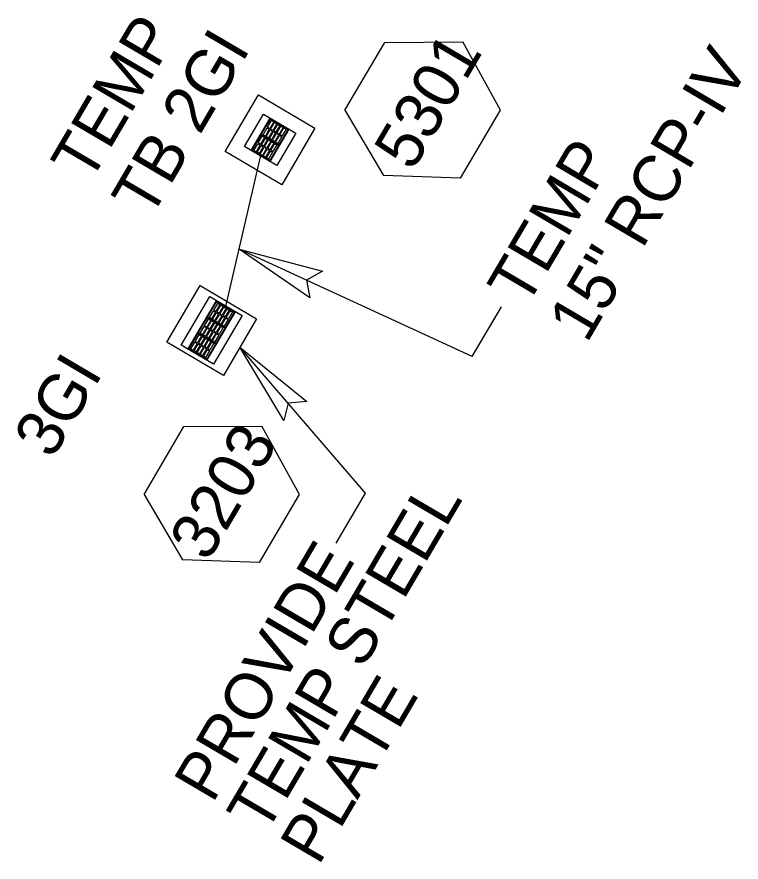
# Model space of a CAD drawing. Extents: x 2214419 to 2238519, y 983271 to 1015868.
# Drawn here: x 2234329 to 2234406.2, y 1008765.9 to 1008856 of the extents above; entities that cross this region are included whole.
import ezdxf

# ---------------------------------------------------------------- set-up
doc = ezdxf.new("R2010")
doc.units = 0
for name, color, linetype in [('Prop Drainage Structure Box Number Symbol CELL', 7, 'Continuous'), ('Prop Drainage Structure Drop Inlet Grate 2 Wide Slots and Sag Grates 840 22 TB CELL', 7, 'Continuous'), ('Prop Drainage Structure Drop Inlet Grate 2 Wide Slots and Sag Grates 840 22 TB Label', 7, 'Continuous'), ('Prop Drainage Structure Drop Inlet Grate 3 Wide Slots and Sag Grates 840 22 CELL', 7, 'Continuous'), ('Prop Drainage Structure Drop Inlet Grate 3 Wide Slots and Sag Grates 840 22 Label', 7, 'Continuous'), ('Prop Drainage Structure Pipe RCP 15in Class IV', 7, 'Continuous'), ('Prop Drainage Structure Pipe RCP 15in Class IV Label', 7, 'Continuous'), ('Prop Drainage Structure Plot Symbol 20 Scale', 7, 'Continuous'), ('Prop Drainage Structure Plot Symbol 20 Scale CELL', 7, 'Continuous'), ('Prop Drainage Structure Plot Symbol 50 Scale', 7, 'Continuous'), ('Prop Drainage Structure Plot Symbol 50 Scale CELL', 7, 'Continuous'), ('Prop Plan Preparation Drainage Notes Label', 7, 'Continuous')]:
    doc.layers.add(name, color=color, linetype=linetype)

msp = doc.modelspace()

# ---------------------------------------------------------------- linework, layer by layer
at = {"layer": 'Prop Drainage Structure Box Number Symbol CELL'}
for p, q in [((2234363.953, 1008846.059), (2234368.209, 1008853.299)), ((2234368.209, 1008853.299), (2234376.525, 1008853.361)), ((2234380.516, 1008846.064), (2234376.525, 1008853.361)), ((2234363.953, 1008846.059), (2234368.061, 1008839.1)), ((2234376.261, 1008838.825), (2234380.516, 1008846.064)), ((2234376.261, 1008838.825), (2234368.061, 1008839.1)), ((2234342.532, 1008805.092), (2234346.788, 1008812.332)), ((2234346.788, 1008812.332), (2234355.104, 1008812.394)), ((2234359.095, 1008805.097), (2234355.104, 1008812.394)), ((2234342.532, 1008805.092), (2234346.639, 1008798.133)), ((2234354.84, 1008797.858), (2234359.095, 1008805.097)), ((2234354.84, 1008797.858), (2234346.639, 1008798.133))]:
    msp.add_line(p, q, dxfattribs=at)
at = {"layer": 'Prop Drainage Structure Drop Inlet Grate 2 Wide Slots and Sag Grates 840 22 TB CELL'}
for p, q in [((2234356.981, 1008844.633), (2234356.981, 1008844.633)), ((2234354.961, 1008843.5), (2234354.961, 1008843.5)), ((2234355.967, 1008842.909), (2234355.967, 1008842.909)), ((2234356.973, 1008842.318), (2234356.973, 1008842.318)), ((2234354.954, 1008841.185), (2234354.954, 1008841.185))]:
    msp.add_line(p, q, dxfattribs=at)
for points in [[(2234357.986, 1008844.042), (2234355.959, 1008840.594), (2234353.948, 1008841.776), (2234355.975, 1008845.225), (2234357.986, 1008844.042)], [(2234357.901, 1008844.02), (2234355.937, 1008840.679), (2234354.033, 1008841.798), (2234355.997, 1008845.139), (2234357.901, 1008844.02), (2234357.901, 1008844.02)], [(2234357.887, 1008844.016), (2234356.915, 1008842.364), (2234355.03, 1008843.472), (2234356.001, 1008845.125), (2234357.887, 1008844.016)], [(2234356.354, 1008844.821), (2234355.931, 1008844.102), (2234355.698, 1008844.24), (2234356.12, 1008844.958), (2234356.354, 1008844.821)], [(2234356.686, 1008844.625), (2234356.264, 1008843.907), (2234356.03, 1008844.044), (2234356.453, 1008844.763), (2234356.686, 1008844.625)], [(2234357.018, 1008844.43), (2234356.596, 1008843.712), (2234356.363, 1008843.849), (2234356.785, 1008844.567), (2234357.018, 1008844.43)], [(2234357.351, 1008844.235), (2234356.928, 1008843.516), (2234356.695, 1008843.654), (2234357.117, 1008844.372), (2234357.351, 1008844.235)], [(2234356.905, 1008842.346), (2234355.934, 1008840.694), (2234354.048, 1008841.802), (2234355.019, 1008843.454), (2234356.905, 1008842.346)], [(2234355.889, 1008844.03), (2234355.467, 1008843.312), (2234355.233, 1008843.449), (2234355.656, 1008844.168), (2234355.889, 1008844.03)], [(2234356.222, 1008843.835), (2234355.799, 1008843.117), (2234355.566, 1008843.254), (2234355.988, 1008843.972), (2234356.222, 1008843.835)], [(2234356.554, 1008843.64), (2234356.131, 1008842.921), (2234355.898, 1008843.059), (2234356.32, 1008843.777), (2234356.554, 1008843.64)], [(2234356.886, 1008843.445), (2234356.464, 1008842.726), (2234356.23, 1008842.863), (2234356.653, 1008843.582), (2234356.886, 1008843.445)], [(2234357.218, 1008843.249), (2234356.796, 1008842.531), (2234356.563, 1008842.668), (2234356.985, 1008843.386), (2234357.218, 1008843.249)], [(2234357.683, 1008844.039), (2234357.261, 1008843.321), (2234357.027, 1008843.458), (2234357.449, 1008844.177), (2234357.683, 1008844.039)], [(2234354.907, 1008842.36), (2234354.485, 1008841.642), (2234354.252, 1008841.779), (2234354.674, 1008842.497), (2234354.907, 1008842.36)], [(2234355.372, 1008843.15), (2234354.95, 1008842.432), (2234354.716, 1008842.569), (2234355.138, 1008843.288), (2234355.372, 1008843.15)], [(2234355.704, 1008842.955), (2234355.282, 1008842.237), (2234355.048, 1008842.374), (2234355.471, 1008843.092), (2234355.704, 1008842.955)], [(2234356.036, 1008842.76), (2234355.614, 1008842.041), (2234355.381, 1008842.179), (2234355.803, 1008842.897), (2234356.036, 1008842.76)], [(2234356.369, 1008842.564), (2234355.946, 1008841.846), (2234355.713, 1008841.983), (2234356.135, 1008842.702), (2234356.369, 1008842.564)], [(2234356.701, 1008842.369), (2234356.279, 1008841.651), (2234356.045, 1008841.788), (2234356.468, 1008842.506), (2234356.701, 1008842.369)], [(2234355.24, 1008842.165), (2234354.817, 1008841.446), (2234354.584, 1008841.584), (2234355.006, 1008842.302), (2234355.24, 1008842.165)], [(2234355.572, 1008841.97), (2234355.15, 1008841.251), (2234354.916, 1008841.388), (2234355.339, 1008842.107), (2234355.572, 1008841.97)], [(2234355.904, 1008841.774), (2234355.482, 1008841.056), (2234355.248, 1008841.193), (2234355.671, 1008841.911), (2234355.904, 1008841.774)], [(2234356.236, 1008841.579), (2234355.814, 1008840.86), (2234355.581, 1008840.998), (2234356.003, 1008841.716), (2234356.236, 1008841.579)]]:
    msp.add_lwpolyline(points, dxfattribs=at)
at = {"layer": 'Prop Drainage Structure Drop Inlet Grate 3 Wide Slots and Sag Grates 840 22 CELL'}
for p, q in [((2234351.249, 1008825.151), (2234351.249, 1008825.151)), ((2234348.738, 1008823.183), (2234348.738, 1008823.183)), ((2234349.744, 1008822.592), (2234349.744, 1008822.592)), ((2234350.75, 1008822), (2234350.75, 1008822)), ((2234348.24, 1008820.032), (2234348.24, 1008820.032))]:
    msp.add_line(p, q, dxfattribs=at)
for points in [[(2234347.234, 1008820.623), (2234350.243, 1008825.742), (2234352.254, 1008824.56), (2234349.245, 1008819.441), (2234347.234, 1008820.623), (2234347.234, 1008820.623)], [(2234347.319, 1008820.646), (2234350.265, 1008825.657), (2234352.169, 1008824.538), (2234349.223, 1008819.527), (2234347.319, 1008820.646)], [(2234349.297, 1008823.99), (2234350.269, 1008825.642), (2234352.155, 1008824.534), (2234351.183, 1008822.881), (2234349.297, 1008823.99)], [(2234349.966, 1008824.757), (2234350.388, 1008825.475), (2234350.622, 1008825.338), (2234350.199, 1008824.62), (2234349.966, 1008824.757)], [(2234349.501, 1008823.967), (2234349.924, 1008824.685), (2234350.157, 1008824.548), (2234349.735, 1008823.83), (2234349.501, 1008823.967)], [(2234349.834, 1008823.771), (2234350.256, 1008824.49), (2234350.489, 1008824.353), (2234350.067, 1008823.634), (2234349.834, 1008823.771)], [(2234350.298, 1008824.562), (2234350.72, 1008825.28), (2234350.954, 1008825.143), (2234350.531, 1008824.424), (2234350.298, 1008824.562)], [(2234350.63, 1008824.366), (2234351.053, 1008825.085), (2234351.286, 1008824.948), (2234350.864, 1008824.229), (2234350.63, 1008824.366)], [(2234350.963, 1008824.171), (2234351.385, 1008824.89), (2234351.618, 1008824.752), (2234351.196, 1008824.034), (2234350.963, 1008824.171)], [(2234351.295, 1008823.976), (2234351.717, 1008824.694), (2234351.951, 1008824.557), (2234351.528, 1008823.838), (2234351.295, 1008823.976)], [(2234348.316, 1008822.32), (2234349.287, 1008823.972), (2234351.173, 1008822.864), (2234350.201, 1008821.211), (2234348.316, 1008822.32)], [(2234348.984, 1008823.087), (2234349.406, 1008823.805), (2234349.64, 1008823.668), (2234349.217, 1008822.949), (2234348.984, 1008823.087)], [(2234349.316, 1008822.891), (2234349.739, 1008823.61), (2234349.972, 1008823.473), (2234349.55, 1008822.754), (2234349.316, 1008822.891)], [(2234350.166, 1008823.576), (2234350.588, 1008824.295), (2234350.821, 1008824.157), (2234350.399, 1008823.439), (2234350.166, 1008823.576)], [(2234350.498, 1008823.381), (2234350.92, 1008824.099), (2234351.154, 1008823.962), (2234350.731, 1008823.244), (2234350.498, 1008823.381)], [(2234350.83, 1008823.186), (2234351.253, 1008823.904), (2234351.486, 1008823.767), (2234351.064, 1008823.048), (2234350.83, 1008823.186)], [(2234348.519, 1008822.296), (2234348.942, 1008823.015), (2234349.175, 1008822.878), (2234348.753, 1008822.159), (2234348.519, 1008822.296)], [(2234348.852, 1008822.101), (2234349.274, 1008822.82), (2234349.507, 1008822.682), (2234349.085, 1008821.964), (2234348.852, 1008822.101)], [(2234349.184, 1008821.906), (2234349.606, 1008822.624), (2234349.84, 1008822.487), (2234349.417, 1008821.769), (2234349.184, 1008821.906)], [(2234349.648, 1008822.696), (2234350.071, 1008823.415), (2234350.304, 1008823.277), (2234349.882, 1008822.559), (2234349.648, 1008822.696)], [(2234349.981, 1008822.501), (2234350.403, 1008823.219), (2234350.636, 1008823.082), (2234350.214, 1008822.364), (2234349.981, 1008822.501)], [(2234350.313, 1008822.305), (2234350.735, 1008823.024), (2234350.969, 1008822.887), (2234350.546, 1008822.168), (2234350.313, 1008822.305)], [(2234347.334, 1008820.649), (2234348.305, 1008822.302), (2234350.191, 1008821.193), (2234349.22, 1008819.541), (2234347.334, 1008820.649)], [(2234348.002, 1008821.416), (2234348.424, 1008822.135), (2234348.658, 1008821.998), (2234348.236, 1008821.279), (2234348.002, 1008821.416)], [(2234348.334, 1008821.221), (2234348.757, 1008821.94), (2234348.99, 1008821.802), (2234348.568, 1008821.084), (2234348.334, 1008821.221)], [(2234348.667, 1008821.026), (2234349.089, 1008821.744), (2234349.322, 1008821.607), (2234348.9, 1008820.889), (2234348.667, 1008821.026)], [(2234349.516, 1008821.711), (2234349.938, 1008822.429), (2234350.172, 1008822.292), (2234349.75, 1008821.573), (2234349.516, 1008821.711)], [(2234349.849, 1008821.515), (2234350.271, 1008822.234), (2234350.504, 1008822.096), (2234350.082, 1008821.378), (2234349.849, 1008821.515)], [(2234347.538, 1008820.626), (2234347.96, 1008821.345), (2234348.193, 1008821.207), (2234347.771, 1008820.489), (2234347.538, 1008820.626)], [(2234347.87, 1008820.431), (2234348.292, 1008821.149), (2234348.526, 1008821.012), (2234348.103, 1008820.294), (2234347.87, 1008820.431)], [(2234348.202, 1008820.236), (2234348.624, 1008820.954), (2234348.858, 1008820.817), (2234348.436, 1008820.098), (2234348.202, 1008820.236)], [(2234348.999, 1008820.83), (2234349.421, 1008821.549), (2234349.655, 1008821.412), (2234349.232, 1008820.693), (2234348.999, 1008820.83)], [(2234349.331, 1008820.635), (2234349.754, 1008821.354), (2234349.987, 1008821.216), (2234349.565, 1008820.498), (2234349.331, 1008820.635)], [(2234348.534, 1008820.04), (2234348.957, 1008820.759), (2234349.19, 1008820.621), (2234348.768, 1008819.903), (2234348.534, 1008820.04)], [(2234348.867, 1008819.845), (2234349.289, 1008820.563), (2234349.522, 1008820.426), (2234349.1, 1008819.708), (2234348.867, 1008819.845)]]:
    msp.add_lwpolyline(points, dxfattribs=at)
at = {"layer": 'Prop Drainage Structure Pipe RCP 15in Class IV'}
msp.add_line((2234351.249, 1008825.151), (2234354.991, 1008841.248), dxfattribs=at)
at = {"layer": 'Prop Drainage Structure Plot Symbol 20 Scale'}
msp.add_lwpolyline([(2234358.705, 1008843.62), (2234356.678, 1008840.171), (2234353.229, 1008842.198), (2234355.257, 1008845.647)], close=True, dxfattribs=at)
at = {"layer": 'Prop Drainage Structure Plot Symbol 20 Scale CELL'}
msp.add_lwpolyline([(2234346.5, 1008821.02), (2234349.541, 1008826.192), (2234352.989, 1008824.165), (2234349.949, 1008818.993)], close=True, dxfattribs=at)
at = {"layer": 'Prop Drainage Structure Plot Symbol 50 Scale'}
msp.add_lwpolyline([(2234360.758, 1008844.153), (2234357.211, 1008838.118), (2234351.176, 1008841.665), (2234354.724, 1008847.7)], close=True, dxfattribs=at)
at = {"layer": 'Prop Drainage Structure Plot Symbol 50 Scale CELL'}
msp.add_lwpolyline([(2234344.954, 1008821.349), (2234348.501, 1008827.383), (2234354.536, 1008823.836), (2234350.988, 1008817.802)], close=True, dxfattribs=at)
at = {"layer": 'Prop Plan Preparation Drainage Notes Label'}
for p, q in [((2234377.509, 1008819.796), (2234352.668, 1008831.257)), ((2234377.509, 1008819.796), (2234380.638, 1008825.118)), ((2234366.159, 1008805.237), (2234352.762, 1008820.819)), ((2234363.03, 1008799.915), (2234366.159, 1008805.237))]:
    msp.add_line(p, q, dxfattribs=at)
for points in [[(2234360.191, 1008826.079), (2234352.668, 1008831.257), (2234361.556, 1008828.918), (2234359.841, 1008827.947)], [(2234357.454, 1008812.984), (2234352.762, 1008820.819), (2234359.875, 1008815), (2234357.912, 1008814.829)]]:
    msp.add_lwpolyline(points, close=True, dxfattribs=at)

# ---------------------------------------------------------------- texts
at = {"layer": 'Prop Drainage Structure Box Number Symbol CELL'}
for s, rotation, p in [('5301', 59.55184, (2234371.144, 1008839.445)), ('3203', 59.55213, (2234349.322, 1008797.797))]:
    msp.add_text(s, height=5, rotation=rotation, dxfattribs=at).set_placement(p)
at = {"layer": 'Prop Drainage Structure Drop Inlet Grate 2 Wide Slots and Sag Grates 840 22 TB Label'}
for s, p in [('TEMP', (2234336.735, 1008838.168)), ('TB 2GI', (2234343.201, 1008834.368))]:
    msp.add_text(s, height=5, rotation=59.55184, dxfattribs=at).set_placement(p)
at = {"layer": 'Prop Drainage Structure Drop Inlet Grate 3 Wide Slots and Sag Grates 840 22 Label'}
msp.add_text('3GI', height=5, rotation=59.55213, dxfattribs=at).set_placement((2234332.746, 1008808.751))
at = {"layer": 'Prop Drainage Structure Pipe RCP 15in Class IV Label'}
for s, p in [('15" RCP-IV ', (2234389.727, 1008821.124)), ('TEMP', (2234383.265, 1008824.93))]:
    msp.add_text(s, height=5, rotation=59.50474, dxfattribs=at).set_placement(p)
at = {"layer": 'Prop Plan Preparation Drainage Notes Label'}
for s, p in [('TEMP STEEL', (2234355.49, 1008768.761)), ('PROVIDE', (2234349.839, 1008772.082)), ('PLATE', (2234361.141, 1008765.441))]:
    msp.add_text(s, height=5, rotation=59.56602, dxfattribs=at).set_placement(p)

doc.saveas('drawing.dxf')
